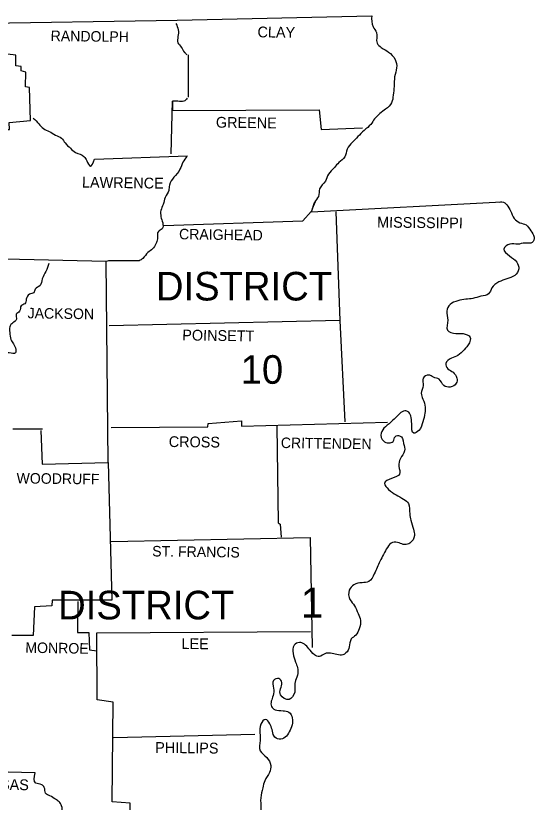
# Model space of a CAD drawing. Extents: x 1096785 to 1382432, y 216169 to 341661.
# Drawn here: x 1214365 to 1218501, y 286518 to 292788 of the extents above; entities that cross this region are included whole.
import ezdxf

# ---------------------------------------------------------------- set-up
doc = ezdxf.new("R2010")
doc.units = 0
for name, color, linetype in [('1', 7, 'Continuous'), ('21', 7, 'Continuous'), ('3', 7, 'Continuous')]:
    doc.layers.add(name, color=color, linetype=linetype)

msp = doc.modelspace()

# ---------------------------------------------------------------- linework, layer by layer
at = {"layer": '1'}
for p, q in [((1216731.4, 291249.9), (1216755.4, 291307.9)), ((1216725.4, 291225.9), (1216749.4, 291299.9)), ((1214341.4, 289493.9), (1214579.4, 289493.9))]:
    msp.add_line(p, q, dxfattribs=at)
for points in [[(1206233.4, 292695.9), (1209467.4, 292693.9), (1212305.4, 292699.9), (1215653.4, 292751.9), (1217205.4, 292787.9)], [(1214565.4, 289481.9), (1214575.4, 289211.9), (1215101.4, 289225.9), (1215087.4, 290829.9), (1214281.4, 290847.9), (1214263.4, 291879.9), (1214315.4, 291881.9), (1214313.4, 291937.9), (1214483.4, 291953.9), (1214475.4, 292215.9), (1214443.4, 292221.9), (1214445.4, 292337.9), (1214409.4, 292347.9), (1214409.4, 292381.9), (1214367.4, 292387.9), (1214367.4, 292473.9), (1214253.4, 292485.9), (1214247.4, 292581.9), (1214225.4, 292595.9), (1214221.4, 292627.9), (1214175.4, 292637.9), (1214177.4, 292661.9), (1214137.4, 292667.9), (1214143.4, 292715.9)], [(1215741.4, 292475.9), (1215741.4, 292137.9)], [(1215605.4, 291687.9), (1215615.4, 292105.9), (1215615.4, 292031.9), (1216785.4, 292037.9), (1216801.4, 291881.9), (1217131.4, 291893.9)], [(1214993.4, 291643.9), (1215735.4, 291669.9)], [(1216725.4, 291225.9), (1218243.4, 291303.9)], [(1215545.4, 291115.9), (1216655.4, 291151.9), (1216721.4, 291227.9)], [(1216917.4, 291223.9), (1216951.4, 290357.9), (1216991.4, 289551.9)], [(1215349.4, 290833.9), (1215105.4, 290833.9), (1215087.4, 290829.9)], [(1216951.4, 290357.9), (1215109.4, 290315.9)], [(1215125.4, 289505.9), (1215897.4, 289509.9), (1215899.4, 289537.9), (1216167.4, 289557.9), (1216167.4, 289515.9), (1217331.4, 289547.9)], [(1216447.4, 289515.9), (1216457.4, 288745.9), (1216475.4, 288733.9), (1216481.4, 288629.9)], [(1215101.4, 289225.9), (1215131.4, 288129.9), (1214655.4, 288127.9), (1214653.4, 288083.9), (1214515.4, 288075.9), (1214503.4, 287847.9), (1214335.4, 287847.9)], [(1215125.4, 288595.9), (1216713.4, 288627.9)], [(1216713.4, 288627.9), (1216729.4, 287751.9)], [(1214859.4, 288117.9), (1214857.4, 287869.9), (1214949.4, 287869.9), (1214953.4, 287731.9), (1215011.4, 287725.9)], [(1215125.4, 286095.9), (1215281.4, 286105.9), (1215279.4, 286511.9), (1215133.4, 286521.9), (1215141.4, 287315.9), (1215015.4, 287333.9), (1215011.4, 287867.9), (1216717.4, 287879.9)], [(1215145.4, 287033.9), (1216273.4, 287061.9)], [(1214519.4, 286751.9), (1213763.4, 286771.9), (1213759.4, 286525.9), (1212229.4, 286519.9)]]:
    msp.add_lwpolyline(points, dxfattribs=at)
for points in [[(1217205.4, 292787.9), (1217215.4, 292699.9), (1217243.4, 292653.9), (1217247.4, 292569.9), (1217281.4, 292533.9), (1217339.4, 292497.9), (1217391.4, 292439.9), (1217403.4, 292371.9), (1217387.4, 292301.9), (1217383.4, 292223.9), (1217375.4, 292155.9), (1217363.4, 292093.9), (1217315.4, 292043.9), (1217269.4, 292007.9), (1217227.4, 291965.9), (1217197.4, 291921.9), (1217145.4, 291873.9), (1217093.4, 291823.9), (1217051.4, 291779.9), (1217009.4, 291723.9), (1216989.4, 291661.9), (1216943.4, 291617.9), (1216907.4, 291577.9), (1216859.4, 291523.9), (1216835.4, 291469.9), (1216789.4, 291407.9), (1216779.4, 291347.9), (1216749.4, 291299.9), (1216747.4, 291291.9)], [(1217205.4, 292787.9), (1217215.4, 292699.9), (1217243.4, 292653.9), (1217247.4, 292569.9), (1217281.4, 292533.9), (1217339.4, 292497.9), (1217391.4, 292439.9), (1217403.4, 292371.9), (1217387.4, 292301.9), (1217383.4, 292223.9), (1217375.4, 292155.9), (1217363.4, 292093.9), (1217315.4, 292043.9), (1217269.4, 292007.9), (1217227.4, 291965.9), (1217197.4, 291921.9), (1217145.4, 291873.9), (1217093.4, 291823.9), (1217051.4, 291779.9), (1217009.4, 291723.9), (1216989.4, 291661.9), (1216943.4, 291617.9), (1216907.4, 291577.9), (1216859.4, 291523.9), (1216835.4, 291469.9), (1216789.4, 291407.9), (1216779.4, 291347.9), (1216749.4, 291299.9), (1216747.4, 291291.9)], [(1215643.4, 292725.9), (1215661.4, 292675.9), (1215659.4, 292621.9), (1215659.4, 292571.9), (1215685.4, 292537.9), (1215711.4, 292495.9), (1215731.4, 292477.9)], [(1215733.4, 292131.9), (1215707.4, 292105.9), (1215657.4, 292105.9), (1215615.4, 292105.9)], [(1214505.4, 291971.9), (1214549.4, 291925.9), (1214587.4, 291887.9), (1214631.4, 291865.9), (1214683.4, 291835.9), (1214729.4, 291811.9), (1214759.4, 291773.9), (1214801.4, 291731.9), (1214843.4, 291697.9), (1214909.4, 291665.9), (1214931.4, 291631.9), (1214961.4, 291589.9), (1214993.4, 291643.9)], [(1215729.4, 291667.9), (1215699.4, 291619.9), (1215675.4, 291563.9), (1215627.4, 291499.9), (1215591.4, 291437.9), (1215585.4, 291395.9), (1215557.4, 291339.9), (1215541.4, 291283.9), (1215523.4, 291235.9), (1215523.4, 291185.9), (1215537.4, 291135.9), (1215533.4, 291089.9), (1215503.4, 291067.9), (1215495.4, 291009.9), (1215483.4, 290969.9), (1215457.4, 290929.9), (1215419.4, 290899.9), (1215379.4, 290853.9), (1215349.4, 290833.9)], [(1218221.4, 291301.9), (1218243.4, 291303.9), (1218311.4, 291231.9), (1218341.4, 291171.9), (1218385.4, 291137.9), (1218435.4, 291119.9), (1218473.4, 291073.9), (1218499.4, 291023.9), (1218485.4, 290979.9), (1218429.4, 290975.9), (1218367.4, 290965.9), (1218307.4, 290967.9), (1218259.4, 290927.9), (1218303.4, 290873.9), (1218361.4, 290823.9), (1218377.4, 290769.9), (1218345.4, 290717.9), (1218281.4, 290689.9), (1218219.4, 290665.9), (1218163.4, 290617.9), (1218137.4, 290571.9), (1218075.4, 290551.9), (1218011.4, 290533.9), (1217955.4, 290527.9), (1217891.4, 290515.9), (1217829.4, 290485.9), (1217803.4, 290433.9), (1217811.4, 290359.9), (1217809.4, 290281.9), (1217875.4, 290255.9), (1217933.4, 290253.9), (1217989.4, 290223.9), (1217983.4, 290179.9), (1217941.4, 290123.9), (1217891.4, 290079.9), (1217841.4, 290057.9), (1217795.4, 290015.9), (1217811.4, 289973.9), (1217853.4, 289945.9), (1217883.4, 289899.9), (1217879.4, 289857.9), (1217831.4, 289827.9), (1217779.4, 289839.9), (1217741.4, 289889.9), (1217697.4, 289905.9), (1217659.4, 289923.9), (1217615.4, 289897.9), (1217615.4, 289839.9), (1217599.4, 289777.9), (1217613.4, 289731.9), (1217631.4, 289667.9), (1217629.4, 289619.9), (1217613.4, 289551.9), (1217579.4, 289481.9), (1217539.4, 289459.9), (1217523.4, 289535.9), (1217515.4, 289597.9), (1217491.4, 289633.9), (1217459.4, 289635.9), (1217417.4, 289605.9), (1217371.4, 289559.9), (1217313.4, 289509.9), (1217279.4, 289459.9), (1217297.4, 289397.9), (1217341.4, 289381.9), (1217375.4, 289393.9), (1217393.4, 289433.9), (1217427.4, 289439.9), (1217459.4, 289377.9)], [(1218221.4, 291301.9), (1218243.4, 291303.9), (1218311.4, 291231.9), (1218341.4, 291171.9), (1218385.4, 291137.9), (1218435.4, 291119.9), (1218473.4, 291073.9), (1218499.4, 291023.9), (1218485.4, 290979.9), (1218429.4, 290975.9), (1218367.4, 290965.9), (1218307.4, 290967.9), (1218259.4, 290927.9), (1218303.4, 290873.9), (1218361.4, 290823.9), (1218377.4, 290769.9), (1218345.4, 290717.9), (1218281.4, 290689.9), (1218219.4, 290665.9), (1218163.4, 290617.9), (1218137.4, 290571.9), (1218075.4, 290551.9), (1218011.4, 290533.9), (1217955.4, 290527.9), (1217891.4, 290515.9), (1217829.4, 290485.9), (1217803.4, 290433.9), (1217811.4, 290359.9), (1217809.4, 290281.9), (1217875.4, 290255.9), (1217933.4, 290253.9), (1217989.4, 290223.9), (1217983.4, 290179.9), (1217941.4, 290123.9), (1217891.4, 290079.9), (1217841.4, 290057.9), (1217795.4, 290015.9), (1217811.4, 289973.9), (1217853.4, 289945.9), (1217883.4, 289899.9), (1217879.4, 289857.9), (1217831.4, 289827.9), (1217779.4, 289839.9), (1217741.4, 289889.9), (1217697.4, 289905.9), (1217659.4, 289923.9), (1217615.4, 289897.9), (1217615.4, 289839.9), (1217599.4, 289777.9), (1217613.4, 289731.9), (1217631.4, 289667.9), (1217629.4, 289619.9), (1217613.4, 289551.9), (1217579.4, 289481.9), (1217539.4, 289459.9), (1217523.4, 289535.9), (1217515.4, 289597.9), (1217491.4, 289633.9), (1217459.4, 289635.9), (1217417.4, 289605.9), (1217371.4, 289559.9), (1217313.4, 289509.9), (1217279.4, 289459.9), (1217297.4, 289397.9), (1217341.4, 289381.9), (1217375.4, 289393.9), (1217393.4, 289433.9), (1217427.4, 289439.9), (1217459.4, 289377.9)], [(1214629.4, 290811.9), (1214605.4, 290749.9), (1214577.4, 290689.9), (1214559.4, 290637.9), (1214521.4, 290607.9), (1214509.4, 290579.9), (1214475.4, 290567.9), (1214449.4, 290527.9), (1214437.4, 290491.9), (1214409.4, 290475.9), (1214395.4, 290431.9), (1214369.4, 290407.9), (1214371.4, 290367.9), (1214341.4, 290339.9), (1214317.4, 290307.9), (1214317.4, 290263.9), (1214327.4, 290205.9), (1214347.4, 290171.9), (1214365.4, 290127.9), (1214363.4, 290099.9), (1214313.4, 290099.9), (1214271.4, 290091.9)], [(1217459.4, 289377.9), (1217467.4, 289319.9), (1217433.4, 289257.9), (1217421.4, 289195.9), (1217427.4, 289133.9), (1217363.4, 289099.9), (1217307.4, 289059.9), (1217339.4, 289011.9), (1217399.4, 288967.9), (1217459.4, 288933.9), (1217497.4, 288899.9), (1217507.4, 288817.9), (1217517.4, 288765.9), (1217537.4, 288693.9), (1217545.4, 288643.9), (1217509.4, 288583.9), (1217467.4, 288571.9), (1217423.4, 288585.9), (1217371.4, 288589.9), (1217329.4, 288549.9), (1217299.4, 288493.9), (1217269.4, 288437.9), (1217247.4, 288389.9), (1217225.4, 288337.9), (1217181.4, 288277.9), (1217127.4, 288267.9), (1217063.4, 288251.9), (1217025.4, 288207.9), (1217031.4, 288133.9), (1217067.4, 288083.9), (1217095.4, 288021.9), (1217115.4, 287967.9), (1217105.4, 287899.9), (1217077.4, 287849.9), (1217041.4, 287819.9), (1217025.4, 287755.9), (1216999.4, 287707.9), (1216975.4, 287691.9), (1216927.4, 287695.9), (1216875.4, 287705.9), (1216831.4, 287701.9), (1216789.4, 287679.9), (1216747.4, 287693.9), (1216703.4, 287741.9), (1216667.4, 287777.9), (1216627.4, 287791.9), (1216585.4, 287769.9), (1216577.4, 287703.9), (1216597.4, 287635.9), (1216615.4, 287543.9), (1216597.4, 287487.9), (1216591.4, 287395.9)], [(1217459.4, 289377.9), (1217467.4, 289319.9), (1217433.4, 289257.9), (1217421.4, 289195.9), (1217427.4, 289133.9), (1217363.4, 289099.9), (1217307.4, 289059.9), (1217339.4, 289011.9), (1217399.4, 288967.9), (1217459.4, 288933.9), (1217497.4, 288899.9), (1217507.4, 288817.9), (1217517.4, 288765.9), (1217537.4, 288693.9), (1217545.4, 288643.9), (1217509.4, 288583.9), (1217467.4, 288571.9), (1217423.4, 288585.9), (1217371.4, 288589.9), (1217329.4, 288549.9), (1217299.4, 288493.9), (1217269.4, 288437.9), (1217247.4, 288389.9), (1217225.4, 288337.9), (1217181.4, 288277.9), (1217127.4, 288267.9), (1217063.4, 288251.9), (1217025.4, 288207.9), (1217031.4, 288133.9), (1217067.4, 288083.9), (1217095.4, 288021.9), (1217115.4, 287967.9), (1217105.4, 287899.9), (1217077.4, 287849.9), (1217041.4, 287819.9), (1217025.4, 287755.9), (1216999.4, 287707.9), (1216975.4, 287691.9), (1216927.4, 287695.9), (1216875.4, 287705.9), (1216831.4, 287701.9), (1216789.4, 287679.9), (1216747.4, 287693.9), (1216703.4, 287741.9), (1216667.4, 287777.9), (1216627.4, 287791.9), (1216585.4, 287769.9), (1216577.4, 287703.9), (1216597.4, 287635.9), (1216615.4, 287543.9), (1216597.4, 287487.9), (1216591.4, 287395.9)], [(1216591.4, 287395.9), (1216545.4, 287337.9), (1216477.4, 287373.9), (1216477.4, 287421.9), (1216487.4, 287471.9), (1216463.4, 287503.9), (1216421.4, 287489.9), (1216421.4, 287427.9), (1216417.4, 287367.9), (1216405.4, 287281.9), (1216433.4, 287255.9), (1216497.4, 287247.9), (1216543.4, 287235.9), (1216571.4, 287189.9), (1216569.4, 287133.9), (1216547.4, 287079.9), (1216515.4, 287035.9), (1216465.4, 287019.9), (1216425.4, 287045.9), (1216409.4, 287097.9), (1216391.4, 287143.9), (1216357.4, 287177.9), (1216321.4, 287139.9), (1216313.4, 287069.9), (1216315.4, 287009.9), (1216315.4, 286927.9), (1216367.4, 286873.9), (1216399.4, 286811.9), (1216389.4, 286755.9), (1216351.4, 286689.9), (1216335.4, 286631.9), (1216319.4, 286553.9), (1216321.4, 286467.9), (1216307.4, 286383.9), (1216279.4, 286327.9), (1216227.4, 286281.9), (1216193.4, 286251.9), (1216165.4, 286221.9), (1216151.4, 286161.9), (1216141.4, 286119.9), (1216103.4, 286069.9), (1216073.4, 286065.9), (1216049.4, 286085.9), (1216041.4, 286119.9), (1216041.4, 286153.9), (1216025.4, 286187.9), (1215975.4, 286201.9), (1215935.4, 286199.9), (1215917.4, 286171.9), (1215943.4, 286093.9), (1215953.4, 286043.9), (1215939.4, 285975.9), (1215947.4, 285967.9), (1215875.4, 285929.9), (1215817.4, 285923.9), (1215769.4, 285909.9), (1215723.4, 285879.9), (1215701.4, 285835.9), (1215669.4, 285799.9), (1215641.4, 285765.9), (1215603.4, 285749.9), (1215561.4, 285757.9), (1215505.4, 285763.9), (1215473.4, 285723.9), (1215483.4, 285665.9), (1215521.4, 285631.9), (1215577.4, 285615.9), (1215635.4, 285619.9), (1215691.4, 285625.9), (1215743.4, 285597.9), (1215733.4, 285543.9), (1215683.4, 285517.9), (1215609.4, 285509.9), (1215549.4, 285515.9), (1215477.4, 285499.9), (1215441.4, 285453.9), (1215461.4, 285383.9), (1215539.4, 285355.9), (1215575.4, 285289.9), (1215577.4, 285227.9), (1215551.4, 285145.9), (1215515.4, 285107.9), (1215445.4, 285091.9), (1215391.4, 285081.9), (1215383.4, 284989.9), (1215359.4, 284943.9), (1215317.4, 284929.9), (1215257.4, 284959.9), (1215221.4, 284973.9), (1215177.4, 284993.9), (1215121.4, 285027.9), (1215079.4, 285021.9), (1215091.4, 284933.9), (1215095.4, 284929.9), (1215143.4, 284863.9), (1215191.4, 284811.9), (1215213.4, 284749.9)], [(1216591.4, 287395.9), (1216545.4, 287337.9), (1216477.4, 287373.9), (1216477.4, 287421.9), (1216487.4, 287471.9), (1216463.4, 287503.9), (1216421.4, 287489.9), (1216421.4, 287427.9), (1216417.4, 287367.9), (1216405.4, 287281.9), (1216433.4, 287255.9), (1216497.4, 287247.9), (1216543.4, 287235.9), (1216571.4, 287189.9), (1216569.4, 287133.9), (1216547.4, 287079.9), (1216515.4, 287035.9), (1216465.4, 287019.9), (1216425.4, 287045.9), (1216409.4, 287097.9), (1216391.4, 287143.9), (1216357.4, 287177.9), (1216321.4, 287139.9), (1216313.4, 287069.9), (1216315.4, 287009.9), (1216315.4, 286927.9), (1216367.4, 286873.9), (1216399.4, 286811.9), (1216389.4, 286755.9), (1216351.4, 286689.9), (1216335.4, 286631.9), (1216319.4, 286553.9), (1216321.4, 286467.9), (1216307.4, 286383.9), (1216279.4, 286327.9), (1216227.4, 286281.9), (1216193.4, 286251.9), (1216165.4, 286221.9), (1216151.4, 286161.9), (1216141.4, 286119.9), (1216103.4, 286069.9), (1216073.4, 286065.9), (1216049.4, 286085.9), (1216041.4, 286119.9), (1216041.4, 286153.9), (1216025.4, 286187.9), (1215975.4, 286201.9), (1215935.4, 286199.9), (1215917.4, 286171.9), (1215943.4, 286093.9), (1215953.4, 286043.9), (1215939.4, 285975.9), (1215947.4, 285967.9), (1215875.4, 285929.9), (1215817.4, 285923.9), (1215769.4, 285909.9), (1215723.4, 285879.9), (1215701.4, 285835.9), (1215669.4, 285799.9), (1215641.4, 285765.9), (1215603.4, 285749.9), (1215561.4, 285757.9), (1215505.4, 285763.9), (1215473.4, 285723.9), (1215483.4, 285665.9), (1215521.4, 285631.9), (1215577.4, 285615.9), (1215635.4, 285619.9), (1215691.4, 285625.9), (1215743.4, 285597.9), (1215733.4, 285543.9), (1215683.4, 285517.9), (1215609.4, 285509.9), (1215549.4, 285515.9), (1215477.4, 285499.9), (1215441.4, 285453.9), (1215461.4, 285383.9), (1215539.4, 285355.9), (1215575.4, 285289.9), (1215577.4, 285227.9), (1215551.4, 285145.9), (1215515.4, 285107.9), (1215445.4, 285091.9), (1215391.4, 285081.9), (1215383.4, 284989.9), (1215359.4, 284943.9), (1215317.4, 284929.9), (1215257.4, 284959.9), (1215221.4, 284973.9), (1215177.4, 284993.9), (1215121.4, 285027.9), (1215079.4, 285021.9), (1215091.4, 284933.9), (1215095.4, 284929.9), (1215143.4, 284863.9), (1215191.4, 284811.9), (1215213.4, 284749.9)], [(1215027.4, 285449.9), (1215053.4, 285481.9), (1215071.4, 285543.9), (1215079.4, 285581.9), (1215085.4, 285647.9), (1215087.4, 285691.9), (1215107.4, 285723.9), (1215117.4, 285783.9), (1215099.4, 285823.9), (1215103.4, 285871.9), (1215107.4, 285925.9), (1215115.4, 285973.9), (1215125.4, 286019.9), (1215125.4, 286049.9), (1215099.4, 286089.9), (1215059.4, 286115.9), (1215027.4, 286125.9), (1215007.4, 286139.9), (1214979.4, 286163.9), (1214951.4, 286211.9), (1214935.4, 286229.9), (1214903.4, 286271.9), (1214871.4, 286295.9), (1214851.4, 286349.9), (1214819.4, 286387.9), (1214775.4, 286403.9), (1214743.4, 286437.9), (1214731.4, 286489.9), (1214711.4, 286521.9), (1214683.4, 286541.9), (1214637.4, 286569.9), (1214603.4, 286589.9), (1214593.4, 286635.9), (1214573.4, 286657.9), (1214525.4, 286669.9), (1214519.4, 286751.9)]]:
    msp.add_spline(points, degree=3, dxfattribs=at)

# ---------------------------------------------------------------- texts
msp.add_text('1', height=240, dxfattribs=at).set_placement((1216639.4, 287989.9))
at = {"layer": '21'}
for s, p in [('DISTRICT', (1215483.4, 290517.9)), ('10', (1216159.4, 289853.9)), ('DISTRICT', (1214703.4, 287975.9))]:
    msp.add_text(s, height=228, dxfattribs=at).set_placement(p)
at = {"layer": '3'}
for s, height, rotation, p in [('CLAY', 85.99, 359.22578, (1216293.4, 292615.9)), ('RANDOLPH', 84.01, 359.25835, (1214643.4, 292585.9)), ('GREENE', 86.02, 359.2361, (1215961.4, 291895.9)), ('LAWRENCE', 86.02, 359.26783, (1214893.4, 291417.9)), ('MISSISSIPPI', 85.992, 359.30972, (1217247.4, 291099.9)), ('CRAIGHEAD', 84.01, 359.11588, (1215667.4, 291005.9)), ('JACKSON', 83.99, 359.13522, (1214459.4, 290375.9)), ('POINSETT', 85.99, 359.19871, (1215693.4, 290199.9)), ('CROSS', 85.99, 359.38394, (1215585.4, 289349.9)), ('CRITTENDEN', 84.01, 359.21302, (1216479.4, 289341.9)), ('WOODRUFF', 83.99, 359.27478, (1214371.4, 289059.9)), ('ST. FRANCIS', 83.988, 359.22157, (1215453.4, 288477.9)), ('MONROE', 83.99, 359.03307, (1214441.4, 287709.9)), ('LEE', 86.02, 359.43273, (1215687.4, 287739.9)), ('PHILLIPS', 85.99, 359.31794, (1215477.4, 286911.9)), ('ARKANSAS', 85.99, 359.26783, (1213843.4, 286621.9))]:
    msp.add_text(s, height=height, rotation=rotation, dxfattribs=at).set_placement(p)

doc.saveas('drawing.dxf')
